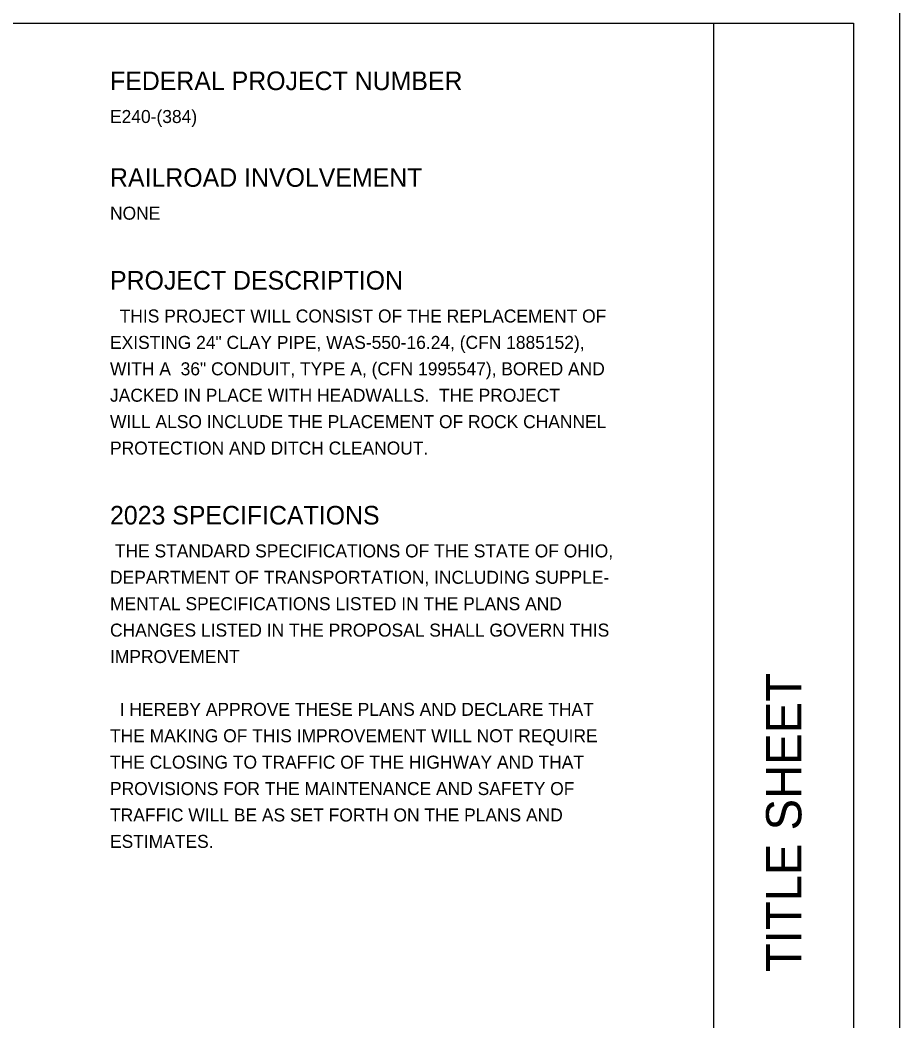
# Model space of a CAD drawing. Extents: x -84548 to 2262448, y -162180 to 525962.
# Drawn here: x 129567 to 179520, y 56851 to 113702 of the extents above; entities that cross this region are included whole.
import ezdxf

# ---------------------------------------------------------------- set-up
doc = ezdxf.new("R2010")
doc.units = 0
for name, color, linetype in [('Default', 7, 'Continuous'), ('GM_X_Adjacent_County', 7, 'Continuous'), ('GM_X_County', 7, 'Continuous'), ('GM_X_Township', 7, 'Continuous')]:
    doc.layers.add(name, color=color, linetype=linetype)

msp = doc.modelspace()

# ---------------------------------------------------------------- linework, layer by layer
at = {"layer": 'GM_X_Adjacent_County'}
msp.add_line((168960, 2640), (168960, 113520), dxfattribs=at)
msp.add_lwpolyline([(7920, 113520), (176880, 113520), (176880, 2640), (7920, 2640)], close=True, dxfattribs=at)
at = {"layer": 'GM_X_Township'}
msp.add_lwpolyline([(0, 0), (179520, 0), (179520, 116160), (0, 116160)], close=True, dxfattribs=at)

# ---------------------------------------------------------------- texts
at = {"layer": 'Default'}
for s, p in [('FEDERAL PROJECT NUMBER', (134675, 109721)), ('RAILROAD INVOLVEMENT', (134675, 104230))]:
    msp.add_text(s, height=1056, dxfattribs=at).set_placement(p)
at = {"layer": 'GM_X_County'}
for s, height, p in [('E240-(384)', 739.2, (134675, 107852)), ('NONE', 739.2, (134675, 102361)), ('PROJECT DESCRIPTION', 1056, (134675, 98390)), ('  THIS PROJECT WILL CONSIST OF THE REPLACEMENT OF', 739.2, (134675, 96521)), ('EXISTING 24" CLAY PIPE, WAS-550-16.24, (CFN 1885152),', 739.2, (134675, 95021)), ('WITH A  36" CONDUIT, TYPE A, (CFN 1995547), BORED AND', 739.2, (134675, 93521)), ('JACKED IN PLACE WITH HEADWALLS.  THE PROJECT', 739.2, (134675, 92021)), ('WILL ALSO INCLUDE THE PLACEMENT OF ROCK CHANNEL', 739.2, (134675, 90521)), ('PROTECTION AND DITCH CLEANOUT.', 739.2, (134675, 89021)), ('2023 SPECIFICATIONS', 1056, (134675, 85050)), (' THE STANDARD SPECIFICATIONS OF THE STATE OF OHIO,', 739.2, (134675, 83181)), ('DEPARTMENT OF TRANSPORTATION, INCLUDING SUPPLE-', 739.2, (134675, 81681)), ('MENTAL SPECIFICATIONS LISTED IN THE PLANS AND', 739.2, (134675, 80181)), ('CHANGES LISTED IN THE PROPOSAL SHALL GOVERN THIS', 739.2, (134675, 78681)), ('IMPROVEMENT', 739.2, (134675, 77181)), ('  I HEREBY APPROVE THESE PLANS AND DECLARE THAT', 739.2, (134675, 74181)), ('THE MAKING OF THIS IMPROVEMENT WILL NOT REQUIRE', 739.2, (134675, 72681)), ('THE CLOSING TO TRAFFIC OF THE HIGHWAY AND THAT', 739.2, (134675, 71181)), ('PROVISIONS FOR THE MAINTENANCE AND SAFETY OF', 739.2, (134675, 69681)), ('TRAFFIC WILL BE AS SET FORTH ON THE PLANS AND', 739.2, (134675, 68181)), ('ESTIMATES.', 739.2, (134675, 66681))]:
    msp.add_text(s, height=height, dxfattribs=at).set_placement(p)
msp.add_text('TITLE SHEET', height=2006.4, rotation=90, dxfattribs=at).set_placement((173923, 59622))

doc.saveas('drawing.dxf')
